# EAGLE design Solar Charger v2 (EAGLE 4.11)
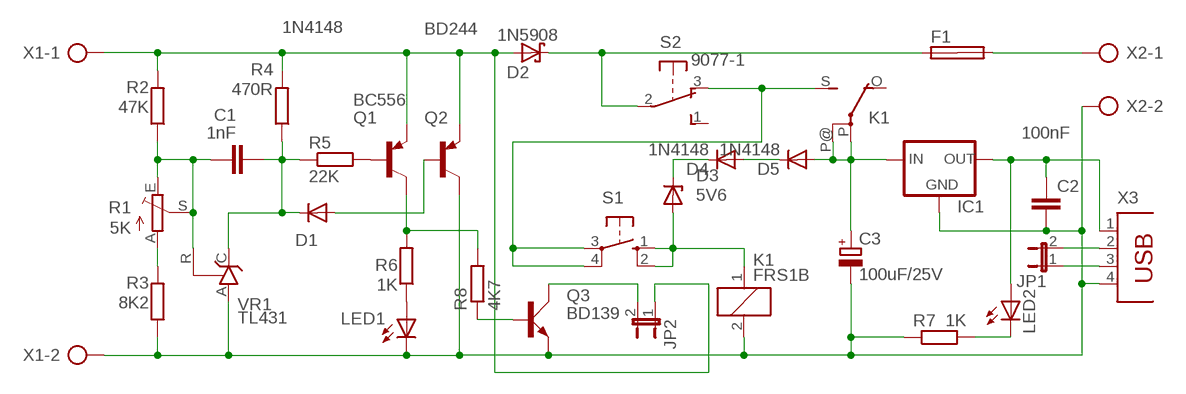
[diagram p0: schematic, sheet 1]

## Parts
C1  1nF  C-EUC025_050-024X070  [C025_050-024X070]
C2  100nF  C-EUC025_050-024X070  [C025_050-024X070]
C3  100uF/25V  CPOL-EUE5-8.5  [E5-8,5]
D1  1N4148  [DO35-10]
D2  1N5908  [C4111-15]
D3  5V6  BZX55  [DO35Z10]
D4  1N4148  [DO35-10]
D5  1N4148  [DO35-10]
F1  SHK20L  [SHK20L]
IC1  78XXL  [78XXL]
JP1  JP1E  [JP1]
JP2  JP1E  [JP1]
K1  FRS1B  [FRS1B]
LED1  LED3MM  [LED3MM]
LED2  LED3MM  [LED3MM]
Q1  BC556  BC328  [TO92-EBC]
Q2  BD244  BD242  [TO220]
Q3  BD139  [TO126AV]
R1  5K  TRIM_EU-CA6V  [CA6V]
R2  47K  R-EU_0207/10  [0207/10]
R3  8K2  R-EU_0207/10  [0207/10]
R4  470R  R-EU_0207/10  [0207/10]
R5  22K  R-EU_0207/10  [0207/10]
R6  1K  R-EU_0207/10  [0207/10]
R7  1K  R-EU_0207/10  [0207/10]
R8  4K7  R-EU_0207/10  [0207/10]
S1  10-XX  [B3F-10XX]
S2  9077-1  [9077-1]
VR1  TL431  TL431CLP  [TO92-CLP]
X1  AK500/2  [AK500/2]
X2  AK500/2  [AK500/2]
X3  PN87520  [PN87520]

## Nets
N$1: R1.A R3.2
N$2: C2.2 C3.- IC1.GND K1.2 LED1.K(C) Q2.2(C) Q3.E R3.1 R7.1 VR1.A X1.2 X2.2 X3.4
N$3: C1.1 R1.E R1.S R2.1 VR1.R
N$5: C1.2 D1.C R4.1 R5.1 VR1.C
N$6: D4.A D5.C
N$7: Q1.B R5.2
N$8: Q1.C R6.2 R8.2
N$9: D1.A Q2.1(B)
N$10: LED1.A R6.1
N$11: D2.C F1.1A S2.2(P)
N$12: F1.2A X2.1
N$13: JP1.2 X3.2
N$14: C2.1 IC1.OUT LED2.A X3.1
N$15: JP1.1 X3.3
N$16: D3.C D4.C
N$17: C3.+ D5.A IC1.IN K1.P(2:P) K1.P@(2:P)
N$18: K1.S(2:S) S1.3(P) S1.4(P1) S2.3(O)
N$19: D3.A K1.1 S1.1(S) S1.2(S1)
N$24: Q3.B R8.1
N$25: JP2.2 Q3.C
N$26: LED2.K(C) R7.2
N$27: D2.A JP2.1 Q1.E Q2.3(E) R2.2 R4.2 X1.1
Unconnected: F1.1B F1.2B K1.O(2:O) S2.1(S)

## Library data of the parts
C1 C2 = rcl:C-EU: CAPACITOR, European symbol
C3 = rcl:CPOL-EU: POLARIZED CAPACITOR, European symbol
D1 D4 D5 = diode:1N4148: DIODE
D2 = diode:1N5908: DIODE
D3 = diode:BZX55: Z DIODE
F1 = fuse:SHK20L: FUSE HOLDER 5 x 20 mm, SH contact, SHH1 Schukat, E1073 Buerklin
IC1 = v-reg:78XXL: VOLTAGE REGULATOR
JP1 JP2 = jumper:JP1E: JUMPER
K1 = relay:FRS1B: RELAY 1 x switch, same as V23101-D6-A201, Siemens
LED1 LED2 = led:LED: LED
Q1 = transistor-pnp:BC328*: PNP Transistror
Q2 = transistor-pnp:BD242: PNP Transistor
Q3 = transistor-power:BD139: NPN TRANSISTOR
R1 = pot:TRIM_EU-: POTENTIOMETER
R2-R8 = rcl:R-EU_: RESISTOR, European symbol
S1 = switch-omron:10-XX: OMRON SWITCH
S2 = switch-misc:9077-1: MARQUARDT SWITCH
VR1 = v-reg:TL431CLP: VOLTAGE REGULATOR
X1 X2 = con-ptr500:AK500/2: CONNECTOR
X3 = con-berg:PN87520: BERG

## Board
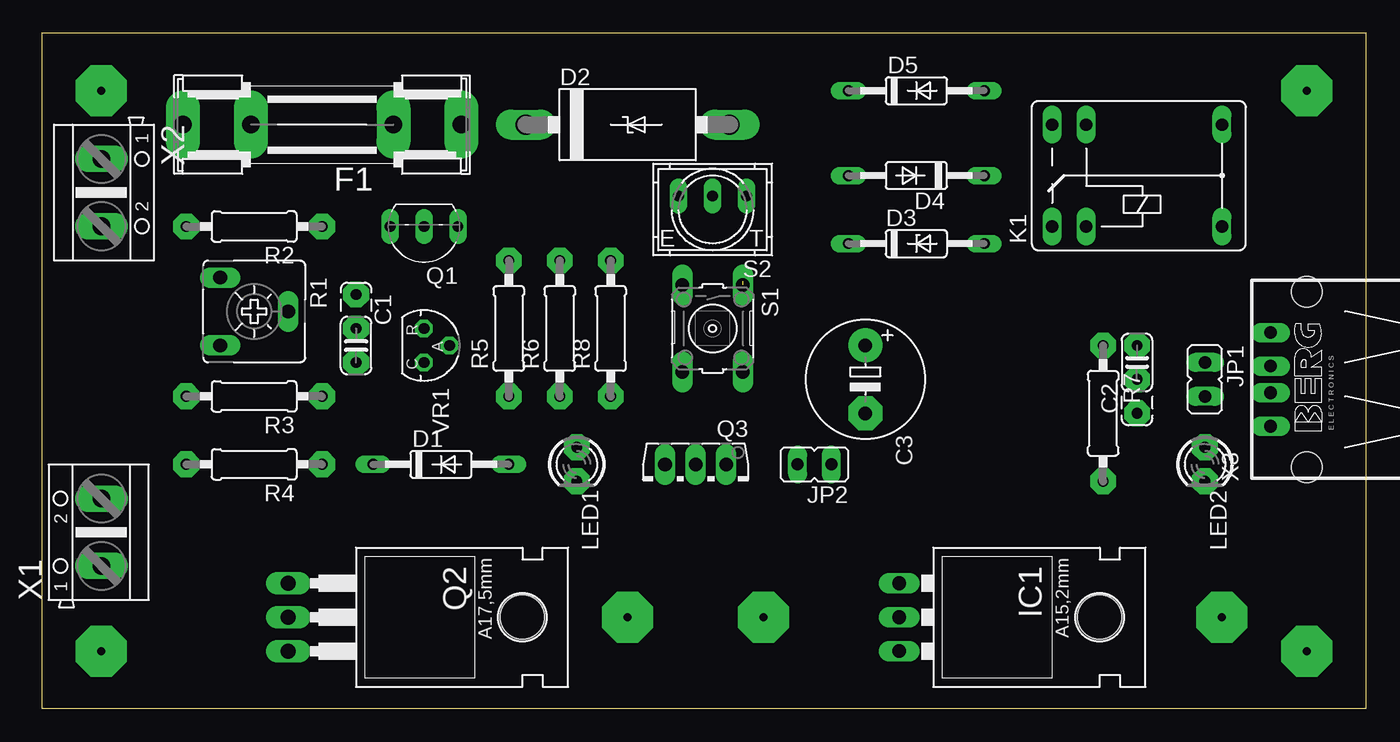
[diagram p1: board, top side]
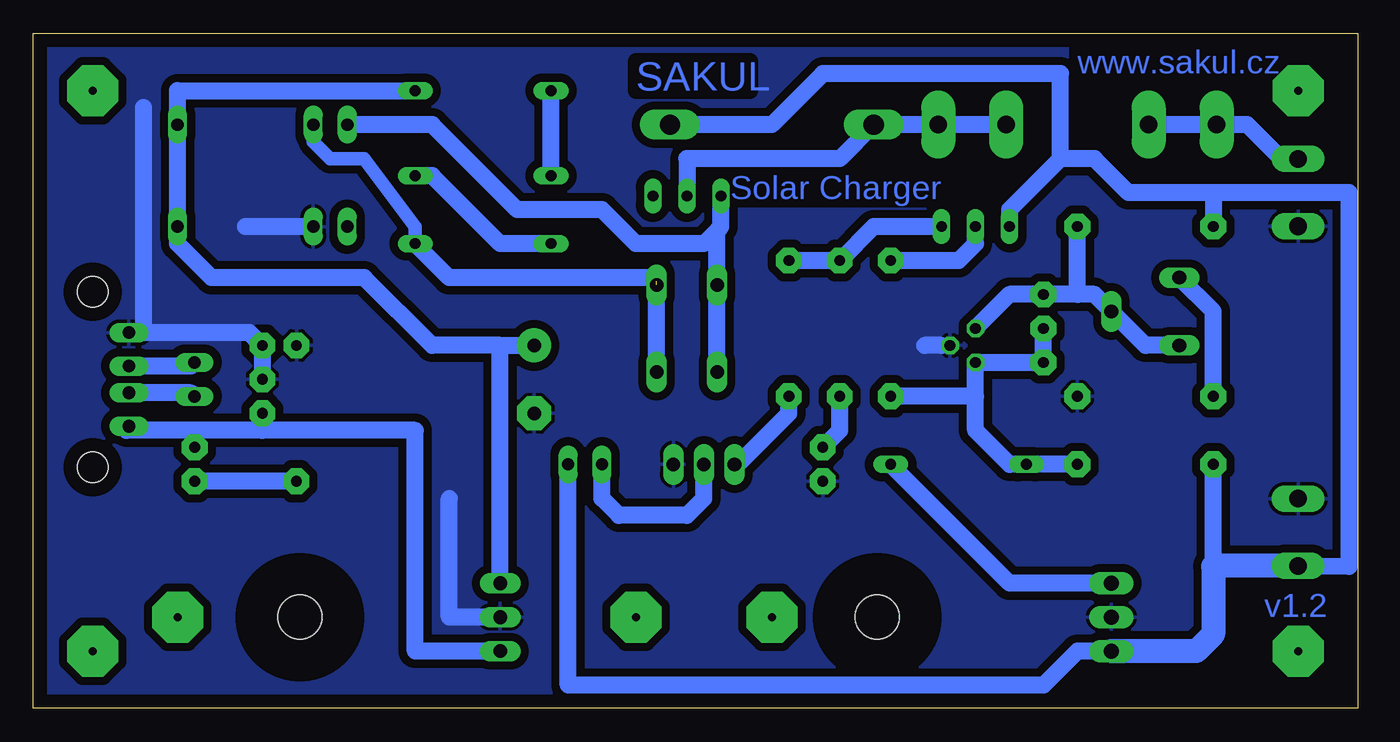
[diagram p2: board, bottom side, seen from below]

Size 99.04 x 50.47 mm. Coordinates in mm from the lower left corner, seen from the top.
Outline: 0,0 99.04,0 99.04,50.47 0,50.47 0,0
Copper layers (1*16): Top 0.035mm / dielectric 1.5mm / Bottom 0.035mm
Design rules "default": minimum track width 10mil, minimum drill 24mil, track to track 8mil, track to pad 8mil, pad to pad 8mil, via to via 8mil, smd to smd 8mil, copper to edge 40mil, drill to drill 8mil, minimum pad ring 10mil, minimum via ring 8mil, stop-mask expansion 4mil, vias tented up to drill 0mil, thermal gap 10mil

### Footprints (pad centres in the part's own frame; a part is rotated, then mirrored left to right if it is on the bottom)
C025_050-024X070 = drill 0.813 pad 1.93 octagon: 1 -3.81,0; 2 -1.27,0; 3 1.27,0
E5-8,5 = drill 1.016 pad 2.54 round: + -2.54,0 | drill 1.016 pad 2.54 octagon: - 2.54,0
DO35-10 = drill 0.813 long: A 5.08,0; C -5.08,0
C4111-15 = drill 1.499 long: A 7.62,0; C -7.62,0
DO35Z10 = drill 0.813 long: A 5.08,0; C -5.08,0
SHK20L = drill 1.321 pad 2.54 long: 1A -10.414,0; 1B -5.334,0; 2A 10.414,0; 2B 5.334,0
78XXL = drill 1.016 long: GND 0,-3.81; IN -2.54,-3.81; OUT 2.54,-3.81 | hole 3.302: 0,11.176
JP1 = drill 0.914 long: 1 0,-1.27; 2 0,1.27
FRS1B = drill 0.914 long: 1 0,3.81; 2 0,-3.81; O -2.54,-3.81; P 10.16,3.81; P@ 10.16,-3.81; S -2.54,3.81
LED3MM = drill 0.813 pad 1.93 octagon: A -1.27,0; K 1.27,0
TO92-EBC = drill 0.813 long: B 0,-1.27; C -2.54,-1.27; E 2.54,-1.27
TO220 = drill 1.118 long: 1 -2.54,-6.35; 2 0,-6.35; 3 2.54,-6.35 | hole 3.302: 0,11.176
TO126AV = drill 1.016 long: B 2.286,-1.27; C 0,-1.27; E -2.286,-1.27
CA6V = drill 1.016 long: A -2.54,-2.54; E 2.54,-2.54; S 0,2.54
0207/10 = drill 0.813 pad 1.93 octagon: 1 -5.08,0; 2 5.08,0
B3F-10XX = drill 1.016 long: 1 -3.251,2.261; 2 3.251,2.261; 3 -3.251,-2.261; 4 3.251,-2.261
9077-1 = drill 0.813 long: 1 -2.54,-1.016; 2 0,-1.016; 3 2.54,-1.016
TO92-CLP = drill 0.813 octagon: A 0,1.905; C 1.27,0; R -1.27,0
AK500/2 = drill 1.321 long: 1 -2.515,0; 2 2.515,0
PN87520 = drill 0.95 long: 1 -3.5,2.71; 2 -1,2.71; 3 1,2.71; 4 3.5,2.71 | hole 2.3: -6.57,0; 6.57,0

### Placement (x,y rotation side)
C1  23.49,27.14 270 top
C2  81.91,25.87 90 top
C3  61.59,24.6 270 top
D1  29.84,18.25 0 top
D2  43.81,43.65 0 top
D3  65.4,34.76 0 top
D4  65.4,39.84 180 top
D5  65.4,46.19 0 top
F1  20.95,43.65 180 top
IC1  67.94,6.82 270 top
JP1  86.99,24.6 180 top
JP2  57.78,18.25 90 top
K1  78.1,39.84 0 top
LED1  40,18.25 270 top
LED2  86.99,18.25 270 top
Q1  28.57,34.76 180 top
Q2  24.76,6.82 270 top
Q3  48.89,16.98 180 top
R1  15.87,29.68 270 top
R2  15.87,36.03 180 top
R3  15.87,23.33 180 top
R4  15.87,18.25 180 top
R5  34.92,28.41 90 top
R6  38.73,28.41 90 top
R7  79.37,22.06 270 top
R8  42.54,28.41 90 top
S1  50.16,28.41 270 top
S2  50.16,37.3 180 top
VR1  28.57,27.14 270 top
X1  4.44,13.17 90 top
X2  4.44,38.57 270 top
X3  94.61,24.6 90 top

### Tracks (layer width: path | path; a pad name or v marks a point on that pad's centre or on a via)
N$1
  Bottom 1.27: R1.A 10.79,29.68 R3.2
N$2
  Bottom 1.27: 31.11,27.14 32.38,27.14 | 90.8,28.1 X3.4 | K1.2 83.18,36.03 | 90.8,28.1 90.8,44.92 | IC1.GND 67.94,6.82 67.94,15.71 | 90.8,28.1 82.87,28.1 81.91,27.14 C2.2
  pour Bottom (isolate 0.61): 0.63,50 98.42,50 98.42,0.47 0.63,0.47
N$3
  Bottom 1.27: 20.95,30.95 19.68,30.95 R1.S 15.87,27.14 R1.E | 20.95,30.95 C1.1 26.03,30.95 VR1.R | 20.95,30.95 R2.1
N$4  (via drill 0.61 pad 3.81)
  other vias: 43.81,6.82
N$5
  Bottom 1.27: R4.1 D1.C 26.03,18.25 28.57,20.79 28.57,23.33 | 28.57,23.33 VR1.C 23.49,25.87 C1.2 | 28.57,23.33 R5.1
N$6
  Bottom 1.27: D4.A D5.C
N$7
  Bottom 1.27: Q1.B 28.57,34.76 29.84,33.49 R5.2
N$8
  Bottom 1.27: Q1.C 36.19,36.03 R6.2 R8.2
N$9
  Bottom 1.27: Q2.1 26.03,9.36 D1.A
N$10
  Bottom 1.27: R6.1 38.73,20.79 LED1.A
N$11
  Bottom 1.27: 26.03,43.65 F1.1A D2.C 38.73,41.11 50.16,41.11 S2.2
N$12
  Bottom 1.27: 15.87,43.65 F1.2A 8.25,43.65 5.68,41.09 X2.1
N$13
  Bottom 1.27: X3.2 87.26,23.6 JP1.2
N$14
  Bottom 1.27: X3.1 91.9,20.96 92.07,20.79 86.99,20.79 | 81.91,20.79 C2.1 | 81.91,20.79 86.99,20.79 | IC1.OUT 70.48,4.28 70.48,20.79 81.91,20.79 | 86.99,20.79 LED2.A
N$15
  Bottom 1.27: X3.3 87.26,25.6 JP1.1
N$16
  Bottom 1.27: D3.C 64.13,34.76 69.21,39.84 D4.C
N$17
  Bottom 1.27: 64.13,27.14 69.21,27.14 74.29,32.22 85.72,32.22 88.26,34.76 K1.P@ K1.P 88.26,46.19 D5.A | 64.13,27.14 C3.+ | IC1.IN 64.13,27.14
N$18
  Bottom 1.27: S1.4 S1.3 47.9,35.75 47.62,36.03 | 47.62,36.03 48.89,34.76 53.97,34.76 56.51,37.3 62.86,37.3 69.21,43.65 K1.S | 47.62,36.03 S2.3
N$19  (1 unrouted)
  Bottom 1.016: K1.1 78.1,42.38 76.83,41.11 74.29,41.11 70.48,36.03 D3.A
  Bottom 1.27: S1.2 52.42,31.94 52.7,32.22 67.94,32.22 D3.A
N$20  (via drill 0.61 pad 3.81)
  other vias: 4.44,46.19
N$21  (via drill 0.61 pad 3.81)
  other vias: 94.61,46.19
N$22  (via drill 0.61 pad 3.81)
  other vias: 94.61,4.28
N$23  (via drill 0.61 pad 3.81)
  other vias: 4.44,4.28
N$24
  Bottom 1.27: Q3.B 46.35,18.25 42.54,22.06 R8.1
N$25
  Bottom 1.27: Q3.C 48.89,15.71 50.16,14.44 55.24,14.44 56.51,15.71 JP2.2
N$26
  Bottom 1.27: R7.2 LED2.K
N$27
  Bottom 1.27: D2.A 43.81,43.65 40,47.46 22.22,47.46 22.22,41.11 | Q1.E 26.03,37.3 22.22,41.11 | 22.22,41.11 19.68,41.11 17.14,38.57 10.79,38.57 | 10.79,38.57 R2.2 | R4.2 10.79,10.63 10.77,10.66 | 10.79,38.57 0.63,38.57 0.63,10.63 3.15,10.66 X1.1 | JP2.1 59.05,1.74 23.49,1.74 20.95,4.28 Q2.3
  Bottom 1.778: Q2.3 12.06,4.28 10.79,5.55 10.79,10.63 | X1.1 4.44,10.63 4.46,10.66 10.77,10.66
N$28  (via drill 0.61 pad 3.81)
  other vias: 53.97,6.82
N$29  (via drill 0.61 pad 3.81)
  other vias: 88.26,6.82

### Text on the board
Bottom: www.sakul.cz | SAKUL | Solar Charger | v1.2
